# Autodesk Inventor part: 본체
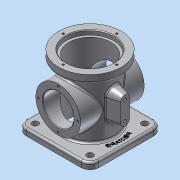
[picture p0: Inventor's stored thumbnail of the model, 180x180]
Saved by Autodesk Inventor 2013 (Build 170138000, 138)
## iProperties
Created: 2021-03
Part Number: 본체
Material: 알루미늄 6061
Document SubType Name: Modeling
Designer: Administrator
Density: 2.71 g/cm^3
Mass: 833.811 g
Surface Area: 863.886 cm^2
Volume: 307.679 cm^3
Author: Administrator
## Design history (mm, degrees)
sketch "스케치1"
  geometry: L1 (-57, -57)-(57, -57); L2 (57, -57)-(57, 57); L3 (57, 57)-(-57, 57); L4 (-57, 57)-(-57, -57); L5 (-57, -57)-(57, 57); L6 (57, -57)-(-57, 57); 1 further point
  constraints: 12 end point, 2 midpoint, 2 parallel, 2 perpendicular, 1 horizontal
  dimensions: "d0" = 114 distance of L2.end L3.end
extrude "돌출1" new body sketch "스케치1" distance "d2" = 10; taper "d3" = 0 deg
sketch "스케치3"
  geometry: C1 r 38 at (0, 0); 1 further point
  constraints: 1 centre point, 1 coincident
  dimensions: "d4" = 76 diameter of C1
extrude "돌출2" join sketch "스케치3" distance "d6" = 88; taper "d7" = 0 deg
sketch "스케치4"
  geometry: C1 r 49 at (0, 0); 1 further point
  constraints: 1 centre point, 1 coincident
  dimensions: "d8" = 98 diameter of C1
extrude "돌출3" join sketch "스케치4" distance "d10" = 13; taper "d11" = 0 deg
sketch "스케치5"
  geometry: L1 (57, 0)-(-57, 0) reference; C1 r 35 at (0, 54); 1 further point
  constraints: 1 centre point, 1 vertical alignment
  dimensions: "d12" = 70 diameter of C1; "d14" = 54 distance from line of L1 C1.centre
extrude "돌출4" join sketch "스케치5" stored distance "d15" = 100; taper "d16" = 0 deg
hole "구멍1" diameter "d19" = 66; stored, may be unused: countersink angle "d23" = 90 deg, drill point angle "d25" = 118 deg; dims "d17" = 10, "d18" = 10, "d20" = 6, "d21" = 74, "d22" = 7, "d24" = 8
hole "구멍2" diameter "d28" = 48; stored, may be unused: countersink angle "d32" = 90 deg, drill point angle "d34" = 118 deg; dims "d26" = 10, "d27" = 10, "d29" = 6, "d30" = 74, "d31" = 7, "d33" = 8
chamfer "모따기1" distance "d35" = 1; stored, may be unused: second distance "d36" = 2, angle "d37" = 45 deg
chamfer "모따기2" distance "d38" = 1; stored, may be unused: second distance "d39" = 2, angle "d40" = 45 deg
fillet "모깎기1" dims "d41" = 3
fillet "모깎기2" dims "d42" = 14
fillet "모깎기3" dims "d43" = 3
node "작업 평면1"
sketch "스케치6"
  geometry: L1 (-7, 41)-(-7, 70); L2 (7, 70)-(7, 41); L3 (-43, 0)-(43, 0) reference; L4 (-80.664, 54)-(67.683, 54); A1 r 7 centre (0, 70) between (7, 70) and (-7, 70); A2 r 7 centre (0, 41) between (-7, 41) and (7, 41); 2 further points
  constraints: 6 end point, 4 point on circle, 4 tangent, 2 centre point, 1 midpoint, 1 parallel, 1 vertical, 1 vertical alignment
  dimensions: "d45" = 14 distance between parallel lines of L1 L2; "d47" = 29 distance of A1.centre A2.centre; "d90" = 54 distance between parallel lines of L3 L4; "d91" = 13 distance from line of A2.centre L4
extrude "돌출5" join sketch "스케치6" stored distance "d49" = 10; taper "d50" = 15 deg
sketch "스케치7"
  geometry: A1 r 42 centre (0, 0) between (0, 42) and (-42, 0); 3 further points
  constraints: 4 point on circle, 2 horizontal alignment, 2 vertical alignment, 1 centre point, 1 coincident
  dimensions: "d51" = 84 diameter of A1
hole "구멍3" sketch "스케치7" at (0, 42), (-42, 0), (0, -42), (42, 0) diameter "d53" = 3.242; stored, may be unused: countersink angle "d57" = 90 deg, drill point angle "d59" = 118 deg; dims "d54" = 6, "d55" = 4, "d56" = 2, "d58" = 8
sketch "스케치8"
  geometry: C1 r 25 at (0, 0) reference; A1 r 31 centre (0, 0) between (0, 31) and (-31, 0); 3 further points
  constraints: 4 point on circle, 2 horizontal alignment, 2 vertical alignment, 1 centre point, 1 coincident
  dimensions: "d60" = 62 diameter of A1
hole "구멍4" sketch "스케치8" at (0, 31), (-31, 0), (0, -31), (31, 0) diameter "d62" = 3.242; stored, may be unused: countersink angle "d66" = 90 deg, drill point angle "d68" = 118 deg; dims "d63" = 6, "d64" = 4, "d65" = 2, "d67" = 8
fillet "모깎기4" dims "d69" = 3
sketch "스케치9"
  geometry: A1 r 7 centre (-41, 0) between (-41, -7) and (-41, 7) reference; A2 r 7 centre (-70, 0) between (-70, 7) and (-70, -7) reference; 3 further points
  constraints: 2 coincident
hole "구멍5" sketch "스케치9" at (-70, 0), (-41, 0) diameter "d70" = 4.134; stored, may be unused: countersink angle "d74" = 90 deg, drill point angle "d76" = 118 deg; dims "d71" = 8, "d72" = 4, "d73" = 2, "d75" = 10
sketch "스케치10"
  geometry: C1 r 50 at (0, 0); 1 further point
  constraints: 1 centre point, 1 coincident, 1 other
  dimensions: "d79" = 100 diameter of C1
feature "엠보싱1" sketch "스케치10" dims "d0" = 114, "d81" = 0.5, "d82" = 0
sketch "스케치11"
  geometry: A1 r 14 centre (-43, 43) between (-43, 57) and (-57, 43) reference; A2 r 14 centre (43, 43) between (57, 43) and (43, 57) reference; A3 r 14 centre (43, -43) between (43, -57) and (57, -43) reference; A4 r 14 centre (-43, -43) between (-57, -43) and (-43, -57) reference; 5 further points
  constraints: 4 coincident
hole "구멍6" sketch "스케치11" at (-43, 43), (43, 43), (43, -43), (-43, -43) diameter "d83" = 10; stored, may be unused: countersink angle "d87" = 90 deg, drill point angle "d89" = 0 deg; dims "d84" = 8, "d85" = 4, "d86" = 2, "d88" = 10
node "솔리드1"
mirror "대칭1"
other parameters: "d44" = 55
